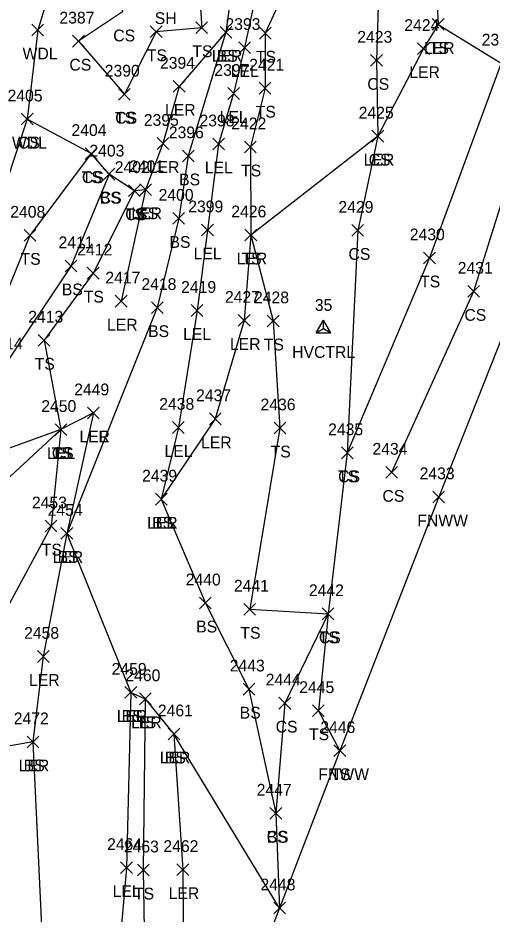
# Model space of a CAD drawing. Extents: x 1483143 to 1488182, y 802902 to 807581.
# Drawn here: x 1487827.4 to 1487907.9, y 806100.3 to 806252.6 of the extents above; entities that cross this region are included whole.
import ezdxf

# ---------------------------------------------------------------- set-up
doc = ezdxf.new("R2010")
doc.units = 0
for name, color, linetype in [('C_A', 7, 'Continuous'), ('C_I', 7, 'Continuous'), ('CPSM', 7, 'Continuous'), ('L_A', 7, 'Continuous'), ('L_I', 7, 'Continuous'), ('L_TIC', 7, 'Continuous'), ('LARO', 7, 'Continuous'), ('LAWA', 7, 'Continuous'), ('LELB', 7, 'Continuous'), ('LFNC', 7, 'Continuous')]:
    doc.layers.add(name, color=color, linetype=linetype)

msp = doc.modelspace()

# ---------------------------------------------------------------- linework, layer by layer
at = {"layer": 'CPSM'}
for p, q in [((1487878.01, 806199.06), (1487879.26, 806201.22)), ((1487880.51, 806199.06), (1487879.26, 806201.22)), ((1487879.26, 806199.78), (1487879.26, 806201.22)), ((1487878.01, 806199.06), (1487879.26, 806199.78)), ((1487879.26, 806199.78), (1487879.26, 806199.78)), ((1487879.26, 806199.78), (1487880.51, 806199.06)), ((1487878.01, 806199.06), (1487880.51, 806199.06))]:
    msp.add_line(p, q, dxfattribs=at)
at = {"layer": 'L_TIC'}
for points in [[(1487829.72, 806249.51), (1487831.72, 806251.51)], [(1487831.72, 806249.51), (1487829.72, 806251.51)], [(1487857.59, 806249.9), (1487859.59, 806251.9)], [(1487859.59, 806249.9), (1487857.59, 806251.9)], [(1487897.76, 806250.46), (1487899.76, 806252.46)], [(1487899.76, 806250.46), (1487897.76, 806252.46)], [(1487897.76, 806250.46), (1487899.76, 806252.46)], [(1487899.76, 806250.46), (1487897.76, 806252.46)], [(1487849.85, 806249.21), (1487851.85, 806251.21)], [(1487851.85, 806249.21), (1487849.85, 806251.21)], [(1487861.7, 806249.12), (1487863.7, 806251.12)], [(1487863.7, 806249.12), (1487861.7, 806251.12)], [(1487861.7, 806249.12), (1487863.7, 806251.12)], [(1487863.7, 806249.12), (1487861.7, 806251.12)], [(1487868.38, 806248.97), (1487870.38, 806250.97)], [(1487870.38, 806248.97), (1487868.38, 806250.97)], [(1487836.65, 806247.61), (1487838.65, 806249.61)], [(1487838.65, 806247.61), (1487836.65, 806249.61)], [(1487864.87, 806246.52), (1487866.87, 806248.52)], [(1487866.87, 806246.52), (1487864.87, 806248.52)], [(1487895.26, 806246.35), (1487897.26, 806248.35)], [(1487897.26, 806246.35), (1487895.26, 806248.35)], [(1487887.27, 806244.35), (1487889.27, 806246.35)], [(1487889.27, 806244.35), (1487887.27, 806246.35)], [(1487853.75, 806239.93), (1487855.75, 806241.93)], [(1487855.75, 806239.93), (1487853.75, 806241.93)], [(1487862.99, 806238.72), (1487864.99, 806240.72)], [(1487864.99, 806238.72), (1487862.99, 806240.72)], [(1487868.35, 806239.62), (1487870.35, 806241.62)], [(1487870.35, 806239.62), (1487868.35, 806241.62)], [(1487844.45, 806238.59), (1487846.45, 806240.59)], [(1487846.45, 806238.59), (1487844.45, 806240.59)], [(1487844.45, 806238.59), (1487846.45, 806240.59)], [(1487846.45, 806238.59), (1487844.45, 806240.59)], [(1487827.92, 806234.37), (1487829.92, 806236.37)], [(1487829.92, 806234.37), (1487827.92, 806236.37)], [(1487827.92, 806234.37), (1487829.92, 806236.37)], [(1487829.92, 806234.37), (1487827.92, 806236.37)], [(1487887.51, 806231.47), (1487889.51, 806233.47)], [(1487889.51, 806231.47), (1487887.51, 806233.47)], [(1487887.51, 806231.47), (1487889.51, 806233.47)], [(1487889.51, 806231.47), (1487887.51, 806233.47)], [(1487851, 806230.22), (1487853, 806232.22)], [(1487853, 806230.22), (1487851, 806232.22)], [(1487860.46, 806230.13), (1487862.46, 806232.13)], [(1487862.46, 806230.13), (1487860.46, 806232.13)], [(1487865.86, 806229.63), (1487867.86, 806231.63)], [(1487867.86, 806229.63), (1487865.86, 806231.63)], [(1487838.79, 806228.5), (1487840.79, 806230.5)], [(1487840.79, 806228.5), (1487838.79, 806230.5)], [(1487838.79, 806228.5), (1487840.79, 806230.5)], [(1487840.79, 806228.5), (1487838.79, 806230.5)], [(1487855.3, 806228.11), (1487857.3, 806230.11)], [(1487857.3, 806228.11), (1487855.3, 806230.11)], [(1487841.83, 806225.01), (1487843.83, 806227.01)], [(1487843.83, 806225.01), (1487841.83, 806227.01)], [(1487841.83, 806225.01), (1487843.83, 806227.01)], [(1487843.83, 806225.01), (1487841.83, 806227.01)], [(1487846.14, 806222.2), (1487848.14, 806224.2)], [(1487848.14, 806222.2), (1487846.14, 806224.2)], [(1487846.14, 806222.2), (1487848.14, 806224.2)], [(1487848.14, 806222.2), (1487846.14, 806224.2)], [(1487848.04, 806222.36), (1487850.04, 806224.36)], [(1487850.04, 806222.36), (1487848.04, 806224.36)], [(1487848.04, 806222.36), (1487850.04, 806224.36)], [(1487850.04, 806222.36), (1487848.04, 806224.36)], [(1487853.67, 806217.49), (1487855.67, 806219.49)], [(1487855.67, 806217.49), (1487853.67, 806219.49)], [(1487828.39, 806214.61), (1487830.39, 806216.61)], [(1487830.39, 806214.61), (1487828.39, 806216.61)], [(1487858.56, 806215.52), (1487860.56, 806217.52)], [(1487860.56, 806215.52), (1487858.56, 806217.52)], [(1487865.93, 806214.67), (1487867.93, 806216.67)], [(1487867.93, 806214.67), (1487865.93, 806216.67)], [(1487865.93, 806214.67), (1487867.93, 806216.67)], [(1487867.93, 806214.67), (1487865.93, 806216.67)], [(1487884.08, 806215.45), (1487886.08, 806217.45)], [(1487886.08, 806215.45), (1487884.08, 806217.45)], [(1487896.28, 806210.77), (1487898.28, 806212.77)], [(1487898.28, 806210.77), (1487896.28, 806212.77)], [(1487835.38, 806209.42), (1487837.38, 806211.42)], [(1487837.38, 806209.42), (1487835.38, 806211.42)], [(1487839.13, 806208.19), (1487841.13, 806210.19)], [(1487841.13, 806208.19), (1487839.13, 806210.19)], [(1487903.77, 806205.09), (1487905.77, 806207.09)], [(1487905.77, 806205.09), (1487903.77, 806207.09)], [(1487843.9, 806203.43), (1487845.9, 806205.43)], [(1487845.9, 806203.43), (1487843.9, 806205.43)], [(1487850.03, 806202.33), (1487852.03, 806204.33)], [(1487852.03, 806202.33), (1487850.03, 806204.33)], [(1487856.78, 806201.84), (1487858.78, 806203.84)], [(1487858.78, 806201.84), (1487856.78, 806203.84)], [(1487864.79, 806200.15), (1487866.79, 806202.15)], [(1487866.79, 806200.15), (1487864.79, 806202.15)], [(1487869.72, 806200.06), (1487871.72, 806202.06)], [(1487871.72, 806200.06), (1487869.72, 806202.06)], [(1487830.79, 806196.78), (1487832.79, 806198.78)], [(1487832.79, 806196.78), (1487830.79, 806198.78)], [(1487839.18, 806184.42), (1487841.18, 806186.42)], [(1487841.18, 806184.42), (1487839.18, 806186.42)], [(1487839.18, 806184.42), (1487841.18, 806186.42)], [(1487841.18, 806184.42), (1487839.18, 806186.42)], [(1487859.88, 806183.43), (1487861.88, 806185.43)], [(1487861.88, 806183.43), (1487859.88, 806185.43)], [(1487833.67, 806181.6), (1487835.67, 806183.6)], [(1487835.67, 806181.6), (1487833.67, 806183.6)], [(1487833.67, 806181.6), (1487835.67, 806183.6)], [(1487835.67, 806181.6), (1487833.67, 806183.6)], [(1487833.67, 806181.6), (1487835.67, 806183.6)], [(1487835.67, 806181.6), (1487833.67, 806183.6)], [(1487853.62, 806181.96), (1487855.62, 806183.96)], [(1487855.62, 806181.96), (1487853.62, 806183.96)], [(1487870.88, 806181.87), (1487872.88, 806183.87)], [(1487872.88, 806181.87), (1487870.88, 806183.87)], [(1487882.32, 806177.65), (1487884.32, 806179.65)], [(1487884.32, 806177.65), (1487882.32, 806179.65)], [(1487882.32, 806177.65), (1487884.32, 806179.65)], [(1487884.32, 806177.65), (1487882.32, 806179.65)], [(1487889.85, 806174.33), (1487891.85, 806176.33)], [(1487891.85, 806174.33), (1487889.85, 806176.33)], [(1487897.86, 806170.16), (1487899.86, 806172.16)], [(1487899.86, 806170.16), (1487897.86, 806172.16)], [(1487850.71, 806169.77), (1487852.71, 806171.77)], [(1487852.71, 806169.77), (1487850.71, 806171.77)], [(1487850.71, 806169.77), (1487852.71, 806171.77)], [(1487852.71, 806169.77), (1487850.71, 806171.77)], [(1487850.71, 806169.77), (1487852.71, 806171.77)], [(1487852.71, 806169.77), (1487850.71, 806171.77)], [(1487831.99, 806165.2), (1487833.99, 806167.2)], [(1487833.99, 806165.2), (1487831.99, 806167.2)], [(1487834.66, 806163.95), (1487836.66, 806165.95)], [(1487836.66, 806163.95), (1487834.66, 806165.95)], [(1487834.66, 806163.95), (1487836.66, 806165.95)], [(1487836.66, 806163.95), (1487834.66, 806165.95)], [(1487858.2, 806152.12), (1487860.2, 806154.12)], [(1487860.2, 806152.12), (1487858.2, 806154.12)], [(1487865.74, 806151.06), (1487867.74, 806153.06)], [(1487867.74, 806151.06), (1487865.74, 806153.06)], [(1487879.05, 806150.29), (1487881.05, 806152.29)], [(1487881.05, 806150.29), (1487879.05, 806152.29)], [(1487879.05, 806150.29), (1487881.05, 806152.29)], [(1487881.05, 806150.29), (1487879.05, 806152.29)], [(1487830.66, 806143.04), (1487832.66, 806145.04)], [(1487832.66, 806143.04), (1487830.66, 806145.04)], [(1487845.54, 806136.93), (1487847.54, 806138.93)], [(1487847.54, 806136.93), (1487845.54, 806138.93)], [(1487845.54, 806136.93), (1487847.54, 806138.93)], [(1487847.54, 806136.93), (1487845.54, 806138.93)], [(1487845.54, 806136.93), (1487847.54, 806138.93)], [(1487847.54, 806136.93), (1487845.54, 806138.93)], [(1487865.6, 806137.49), (1487867.6, 806139.49)], [(1487867.6, 806137.49), (1487865.6, 806139.49)], [(1487848, 806135.84), (1487850, 806137.84)], [(1487850, 806135.84), (1487848, 806137.84)], [(1487848, 806135.84), (1487850, 806137.84)], [(1487850, 806135.84), (1487848, 806137.84)], [(1487871.71, 806135.11), (1487873.71, 806137.11)], [(1487873.71, 806135.11), (1487871.71, 806137.11)], [(1487877.4, 806133.82), (1487879.4, 806135.82)], [(1487879.4, 806133.82), (1487877.4, 806135.82)], [(1487852.87, 806129.86), (1487854.87, 806131.86)], [(1487854.87, 806129.86), (1487852.87, 806131.86)], [(1487852.87, 806129.86), (1487854.87, 806131.86)], [(1487854.87, 806129.86), (1487852.87, 806131.86)], [(1487828.9, 806128.52), (1487830.9, 806130.52)], [(1487830.9, 806128.52), (1487828.9, 806130.52)], [(1487828.9, 806128.52), (1487830.9, 806130.52)], [(1487830.9, 806128.52), (1487828.9, 806130.52)], [(1487881.05, 806127.03), (1487883.05, 806129.03)], [(1487883.05, 806127.03), (1487881.05, 806129.03)], [(1487881.05, 806127.03), (1487883.05, 806129.03)], [(1487883.05, 806127.03), (1487881.05, 806129.03)], [(1487870.18, 806116.39), (1487872.18, 806118.39)], [(1487872.18, 806116.39), (1487870.18, 806118.39)], [(1487870.18, 806116.39), (1487872.18, 806118.39)], [(1487872.18, 806116.39), (1487870.18, 806118.39)], [(1487844.8, 806107.14), (1487846.8, 806109.14)], [(1487846.8, 806107.14), (1487844.8, 806109.14)], [(1487847.66, 806106.74), (1487849.66, 806108.74)], [(1487849.66, 806106.74), (1487847.66, 806108.74)], [(1487854.38, 806106.81), (1487856.38, 806108.81)], [(1487856.38, 806106.81), (1487854.38, 806108.81)], [(1487870.82, 806100.28), (1487872.82, 806102.28)], [(1487872.82, 806100.28), (1487870.82, 806102.28)], [(1487870.82, 806100.28), (1487872.82, 806102.28)], [(1487872.82, 806100.28), (1487870.82, 806102.28)]]:
    msp.add_lwpolyline(points, dxfattribs=at)
at = {"layer": 'LARO'}
for points in [[(1487909.56, 806290.7), (1487905.87, 806296.52), (1487904.09, 806299.8), (1487889.74, 806303.05), (1487875.49, 806288.06), (1487869.58, 806264.86), (1487865.87, 806247.52), (1487863.99, 806239.72), (1487861.46, 806231.13), (1487859.56, 806216.52), (1487857.78, 806202.84), (1487854.62, 806182.96), (1487851.71, 806170.77)], [(1487909.56, 806290.7), (1487905.83, 806276.22), (1487898.18, 806262.8), (1487898.76, 806251.46), (1487896.26, 806247.35), (1487888.51, 806232.47), (1487866.93, 806215.67), (1487865.79, 806201.15), (1487860.88, 806184.43), (1487851.71, 806170.77)], [(1487865.1, 806267.91), (1487862.7, 806250.12), (1487854.75, 806240.93), (1487852, 806231.22), (1487849.04, 806223.36), (1487844.9, 806204.43)], [(1487840.18, 806185.42), (1487834.67, 806182.6), (1487822.58, 806178.25), (1487811.01, 806152.68), (1487805.8, 806138.73), (1487805.57, 806125.09), (1487812.67, 806122.39), (1487808.76, 806106.51), (1487799.94, 806095.08), (1487791.75, 806069.31), (1487789.16, 806039.67), (1487787.77, 806021.85), (1487782.39, 806010.38), (1487772.44, 806000.5), (1487764.14, 805988.07), (1487767.26, 805965.45), (1487766, 805943.66), (1487763.65, 805933.94), (1487758.69, 805910.3), (1487765.4, 805900.12), (1487775.65, 805902.89)], [(1487840.18, 806185.42), (1487835.66, 806164.95), (1487831.66, 806144.04), (1487829.9, 806129.52), (1487831.5, 806094.6), (1487833.19, 806067.23), (1487831.83, 806052.01), (1487826.75, 806039.7), (1487819.72, 806036.65), (1487826.17, 806020.88), (1487825.98, 806002.41), (1487822.1, 805985.51), (1487816.73, 805985.65), (1487813.1, 806007.48), (1487813.04, 806016.36), (1487804.68, 806014.34), (1487795.81, 805998.55), (1487803.82, 805982.4), (1487790.91, 805980.55), (1487784.69, 805981.84), (1487782.27, 805971.68), (1487795.22, 805970.97), (1487803.27, 805964.29)], [(1487846.54, 806137.93), (1487845.8, 806108.14), (1487843.73, 806084.2), (1487843.56, 806067.38), (1487839.59, 806046.99), (1487833.11, 806020.48)], [(1487846.54, 806137.93), (1487849, 806136.84), (1487853.87, 806130.86), (1487855.38, 806107.81), (1487855.52, 806084.77), (1487853.77, 806056.92)]]:
    msp.add_lwpolyline(points, dxfattribs=at)
at = {"layer": 'LAWA'}
msp.add_lwpolyline([(1487942.37, 806424.18), (1487942.13, 806400.96), (1487924.66, 806393.36), (1487906.74, 806373.16), (1487899.59, 806370.18), (1487890.83, 806350.54), (1487893.79, 806329.46), (1487876.29, 806319.09), (1487863.09, 806294.65), (1487840.52, 806269.33), (1487843.55, 806264.22), (1487833.59, 806259.9), (1487830.72, 806250.51), (1487828.92, 806235.37), (1487823.44, 806218.85), (1487816.5, 806198.3), (1487812.31, 806191.59), (1487811.73, 806182.07)], dxfattribs=at)
at = {"layer": 'LELB'}
for points in [[(1487940.19, 806330.57), (1487936.41, 806308.22), (1487924.68, 806281.58), (1487917.48, 806273.83), (1487907.89, 806261.98), (1487917.31, 806246.1), (1487904.77, 806206.09), (1487890.85, 806175.33)], [(1487905.87, 806296.52), (1487899.31, 806298.27), (1487896, 806290.59), (1487887.31, 806283.36), (1487877.52, 806267.63), (1487869.38, 806249.97), (1487869.35, 806240.62), (1487866.86, 806230.63), (1487866.93, 806215.67), (1487870.72, 806201.06), (1487871.88, 806182.87), (1487866.74, 806152.06), (1487880.05, 806151.29), (1487878.4, 806134.82), (1487882.05, 806128.03)], [(1487887.31, 806283.36), (1487888.96, 806267.66), (1487888.27, 806245.35), (1487888.51, 806232.47), (1487885.08, 806216.45), (1487883.32, 806178.65), (1487880.05, 806151.29), (1487872.71, 806136.11), (1487871.18, 806117.39)], [(1487857.3, 806269.9), (1487858.59, 806250.9), (1487850.85, 806250.21), (1487845.45, 806239.59)], [(1487843.55, 806264.22), (1487845.11, 806253.58), (1487837.65, 806248.61), (1487845.45, 806239.59)], [(1487898.76, 806251.46), (1487909.47, 806244.87), (1487897.28, 806211.77), (1487883.32, 806178.65)], [(1487862.7, 806250.12), (1487856.3, 806229.11), (1487854.67, 806218.49), (1487851.03, 806203.33), (1487835.66, 806164.95), (1487846.54, 806137.93)], [(1487849.04, 806223.36), (1487847.14, 806223.2), (1487842.83, 806226.01), (1487839.79, 806229.5), (1487828.92, 806235.37)], [(1487839.79, 806229.5), (1487829.39, 806215.61), (1487824.73, 806204.13), (1487816.5, 806198.3)], [(1487842.83, 806226.01), (1487836.38, 806210.42), (1487824.92, 806193.22), (1487812.31, 806191.59), (1487822.58, 806178.25)], [(1487847.14, 806223.2), (1487840.13, 806209.19), (1487831.79, 806197.78), (1487834.67, 806182.6), (1487832.99, 806166.2), (1487821.17, 806144.33), (1487820.15, 806130.73), (1487817.72, 806127.4), (1487821.03, 806122.4), (1487825.17, 806095.15), (1487826.04, 806071.21), (1487819.68, 806058.95), (1487818.7, 806047.19), (1487815.48, 806048.93), (1487807.41, 806062.56), (1487796.67, 806073.08)], [(1487834.67, 806182.6), (1487822.16, 806171.09), (1487812.07, 806151.71), (1487813.69, 806131.97), (1487805.57, 806125.09)], [(1487851.71, 806170.77), (1487859.2, 806153.12), (1487866.6, 806138.49), (1487871.18, 806117.39), (1487871.82, 806101.28), (1487853.87, 806130.86)], [(1487849, 806136.84), (1487848.66, 806107.74), (1487849.03, 806084.3), (1487847.55, 806054.83)], [(1487829.9, 806129.52), (1487817.72, 806127.4), (1487812.67, 806122.39)]]:
    msp.add_lwpolyline(points, dxfattribs=at)
at = {"layer": 'LFNC'}
msp.add_lwpolyline([(1487987.25, 806418.51), (1487973.91, 806378.22), (1487965.8, 806351.13), (1487955.89, 806321.22), (1487948.76, 806302.23), (1487939.1, 806274.15), (1487927.43, 806243.4), (1487914.16, 806209.81), (1487898.86, 806171.16), (1487882.05, 806128.03), (1487871.82, 806101.28), (1487863.45, 806079.83), (1487853.77, 806056.92)], dxfattribs=at)

# ---------------------------------------------------------------- texts
at = {"layer": 'C_A'}
msp.add_text('HVCTRL', height=2, dxfattribs=at).set_placement((1487873.95, 806194.78))
at = {"layer": 'C_I'}
msp.add_text('35', height=2, dxfattribs=at).set_placement((1487877.8, 806202.78))
at = {"layer": 'L_A'}
for s, p in [('SH', (1487850.6, 806251.53)), ('CS', (1487843.55, 806248.58)), ('LER', (1487896.34, 806246.46)), ('TS', (1487897.17, 806246.46)), ('WDL', (1487828.14, 806245.51)), ('TS', (1487849.26, 806245.21)), ('TS', (1487857, 806245.9)), ('LER', (1487860.29, 806245.12)), ('BS', (1487861.14, 806245.12)), ('TS', (1487867.79, 806244.97)), ('CS', (1487836.1, 806243.61)), ('LEL', (1487863.51, 806242.52)), ('LER', (1487893.85, 806242.35)), ('CS', (1487886.72, 806240.35)), ('LER', (1487852.34, 806235.93)), ('TS', (1487867.76, 806235.62)), ('TS', (1487843.86, 806234.59)), ('CS', (1487843.89, 806234.59)), ('LEL', (1487861.62, 806234.72)), ('WDL', (1487826.34, 806230.37)), ('CS', (1487827.37, 806230.37)), ('LER', (1487886.1, 806227.47)), ('CS', (1487886.95, 806227.47)), ('LER', (1487849.58, 806226.22)), ('LEL', (1487859.1, 806226.13)), ('TS', (1487865.27, 806225.63)), ('TS', (1487838.2, 806224.5)), ('CS', (1487838.23, 806224.5)), ('BS', (1487854.74, 806224.11)), ('CS', (1487841.27, 806221.01)), ('BS', (1487841.27, 806221.01)), ('TS', (1487845.55, 806218.2)), ('CS', (1487845.58, 806218.2)), ('LER', (1487846.62, 806218.36)), ('CS', (1487847.48, 806218.36)), ('BS', (1487853.11, 806213.49)), ('LEL', (1487857.2, 806211.52)), ('CS', (1487883.52, 806211.45)), ('TS', (1487827.8, 806210.61)), ('LER', (1487864.51, 806210.67)), ('TS', (1487865.34, 806210.67)), ('TS', (1487895.69, 806206.77)), ('BS', (1487834.82, 806205.42)), ('TS', (1487838.54, 806204.19)), ('CS', (1487903.21, 806201.09)), ('LER', (1487842.48, 806199.43)), ('BS', (1487849.47, 806198.33)), ('LEL', (1487855.42, 806197.84)), ('LER', (1487863.37, 806196.15)), ('TS', (1487869.13, 806196.06)), ('TS', (1487830.2, 806192.78)), ('LER', (1487837.77, 806180.42)), ('LEL', (1487837.82, 806180.42)), ('LER', (1487858.46, 806179.43)), ('LEL', (1487852.26, 806177.96)), ('TS', (1487870.29, 806177.87)), ('LEL', (1487832.3, 806177.6)), ('TS', (1487833.08, 806177.6)), ('CS', (1487833.11, 806177.6)), ('TS', (1487881.73, 806173.65)), ('CS', (1487881.76, 806173.65)), ('CS', (1487889.29, 806170.33)), ('LER', (1487849.3, 806165.77)), ('LEL', (1487849.35, 806165.77)), ('BS', (1487850.16, 806165.77)), ('FNWW', (1487895.21, 806166.16)), ('TS', (1487831.4, 806161.2)), ('LER', (1487833.24, 806159.95)), ('BS', (1487834.1, 806159.95)), ('BS', (1487857.64, 806148.12)), ('TS', (1487865.15, 806147.06)), ('TS', (1487878.45, 806146.29)), ('CS', (1487878.49, 806146.29)), ('LER', (1487829.24, 806139.04)), ('LER', (1487844.12, 806132.93)), ('LEL', (1487844.18, 806132.93)), ('BS', (1487844.98, 806132.93)), ('BS', (1487865.04, 806133.49)), ('LER', (1487846.58, 806131.84)), ('TS', (1487847.41, 806131.84)), ('CS', (1487871.15, 806131.11)), ('TS', (1487876.81, 806129.82)), ('LER', (1487827.48, 806124.52)), ('BS', (1487828.34, 806124.52)), ('LER', (1487851.45, 806125.86)), ('BS', (1487852.31, 806125.86)), ('FNWW', (1487878.39, 806123.03)), ('TS', (1487880.46, 806123.03)), ('CS', (1487869.62, 806112.39)), ('BS', (1487869.62, 806112.39)), ('LEL', (1487843.44, 806103.14)), ('TS', (1487847.07, 806102.74)), ('LER', (1487852.96, 806102.81))]:
    msp.add_text(s, height=2, dxfattribs=at).set_placement(p)
at = {"layer": 'L_I'}
for s, p in [('2387', (1487834.4, 806251.61)), ('2393', (1487862.61, 806250.52)), ('2424', (1487893, 806250.35)), ('2423', (1487885.01, 806248.35)), ('2369', (1487906.15, 806247.87)), ('2394', (1487851.49, 806243.93)), ('2421', (1487866.65, 806243.62)), ('2390', (1487842.1, 806242.59)), ('2390', (1487842.1, 806242.59)), ('2397', (1487860.73, 806242.72)), ('2405', (1487825.59, 806238.37)), ('2405', (1487825.59, 806238.37)), ('2395', (1487848.74, 806234.22)), ('2398', (1487858.2, 806234.13)), ('2425', (1487885.25, 806235.47)), ('2425', (1487885.25, 806235.47)), ('2422', (1487863.6, 806233.63)), ('2404', (1487836.45, 806232.5)), ('2404', (1487836.45, 806232.5)), ('2396', (1487852.99, 806232.11)), ('2403', (1487839.49, 806229.01)), ('2403', (1487839.49, 806229.01)), ('2402', (1487843.8, 806226.2)), ('2402', (1487843.8, 806226.2)), ('2401', (1487846.26, 806226.36)), ('2401', (1487846.26, 806226.36)), ('2400', (1487851.25, 806221.49)), ('2399', (1487856.29, 806219.52)), ('2429', (1487881.81, 806219.45)), ('2408', (1487826.05, 806218.61)), ('2426', (1487863.61, 806218.67)), ('2426', (1487863.61, 806218.67)), ('2430', (1487893.93, 806214.77)), ('2411', (1487834.25, 806213.42)), ('2412', (1487837.44, 806212.19)), ('2431', (1487902.08, 806209.09)), ('2417', (1487842.21, 806207.43)), ('2418', (1487848.33, 806206.33)), ('2419', (1487855.08, 806205.84)), ('2427', (1487862.53, 806204.15)), ('2428', (1487867.46, 806204.06)), ('2413', (1487829.1, 806200.78)), ('2414', (1487822.23, 806196.22)), ('2449', (1487836.91, 806188.42)), ('2449', (1487836.91, 806188.42)), ('2437', (1487857.62, 806187.43)), ('2450', (1487831.32, 806185.6)), ('2450', (1487831.32, 806185.6)), ('2450', (1487831.32, 806185.6)), ('2438', (1487851.36, 806185.96)), ('2436', (1487868.57, 806185.87)), ('2435', (1487880.06, 806181.65)), ('2435', (1487880.06, 806181.65)), ('2434', (1487887.59, 806178.33)), ('2439', (1487848.45, 806173.77)), ('2439', (1487848.45, 806173.77)), ('2439', (1487848.45, 806173.77)), ('2433', (1487895.6, 806174.16)), ('2453', (1487829.73, 806169.2)), ('2454', (1487832.4, 806167.95)), ('2454', (1487832.4, 806167.95)), ('2440', (1487855.86, 806156.12)), ('2441', (1487864.05, 806155.06)), ('2442', (1487876.79, 806154.29)), ('2442', (1487876.79, 806154.29)), ('2458', (1487828.4, 806147.04)), ('2443', (1487863.34, 806141.49)), ('2459', (1487843.27, 806140.93)), ('2459', (1487843.27, 806140.93)), ('2459', (1487843.27, 806140.93)), ('2460', (1487845.61, 806139.84)), ('2460', (1487845.61, 806139.84)), ('2444', (1487869.45, 806139.11)), ('2445', (1487875.15, 806137.82)), ('2461', (1487851.13, 806133.86)), ('2461', (1487851.13, 806133.86)), ('2472', (1487826.64, 806132.52)), ('2472', (1487826.64, 806132.52)), ('2446', (1487878.73, 806131.03)), ('2446', (1487878.73, 806131.03)), ('2447', (1487867.92, 806120.39)), ('2447', (1487867.92, 806120.39)), ('2464', (1487842.5, 806111.14)), ('2463', (1487845.35, 806110.74)), ('2462', (1487852.07, 806110.81)), ('2448', (1487868.56, 806104.28)), ('2448', (1487868.56, 806104.28))]:
    msp.add_text(s, height=2, dxfattribs=at).set_placement(p)

doc.saveas('drawing.dxf')
